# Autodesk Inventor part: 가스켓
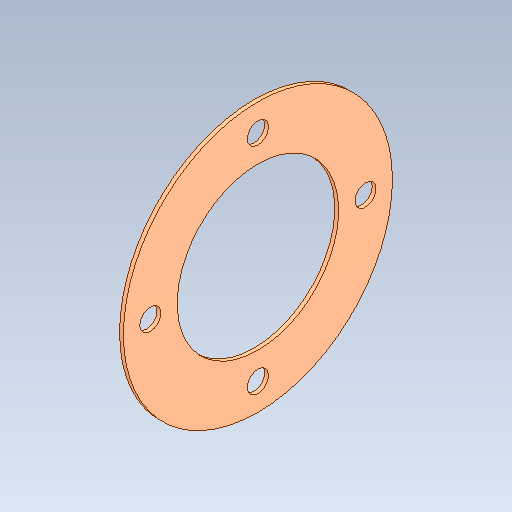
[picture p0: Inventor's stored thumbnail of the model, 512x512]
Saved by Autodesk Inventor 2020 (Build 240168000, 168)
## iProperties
Created: 2024-09
Part Number: 가스켓
Material: 스테인리스스틸
Document SubType Name: Modeling
Designer: oem
Density: 8 g/cm^3
Appearance: 기본값
Author: jhkim
Sending System: Autodesk Inventor 2025
Preprocessor: ST-DEVELOPER v20
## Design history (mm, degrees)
feature "솔리드1"
node "솔리드2"
